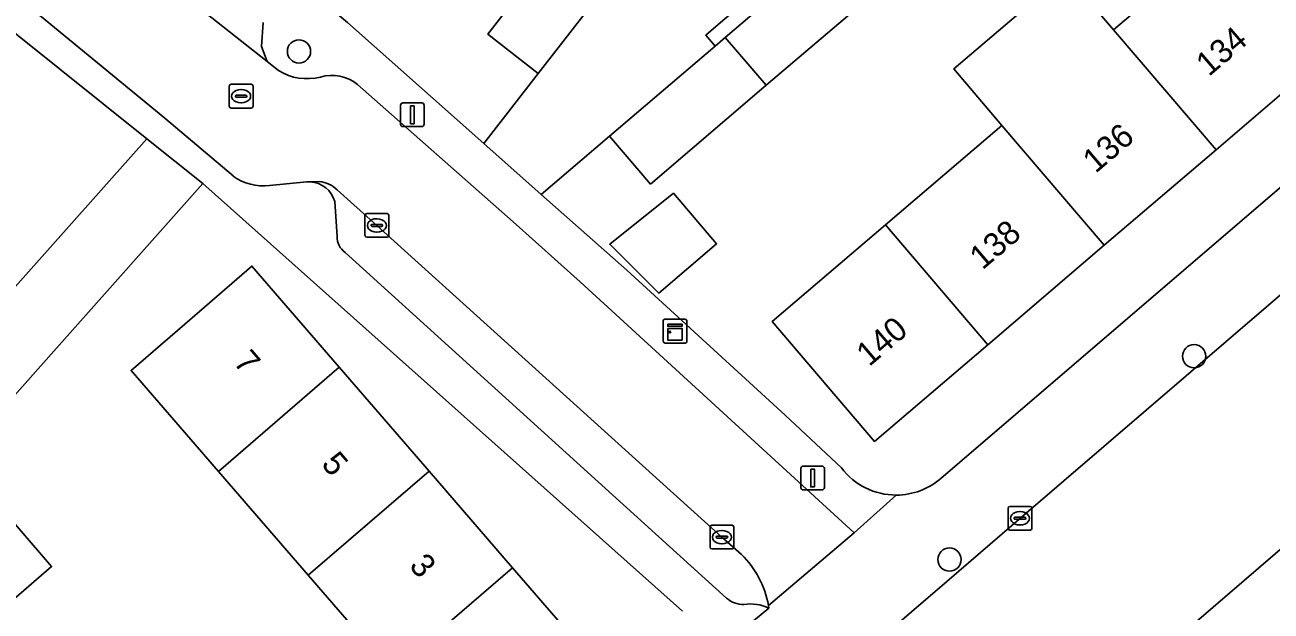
# Model space of a CAD drawing. Extents: x 159039 to 160102, y 381214 to 382524.
# Drawn here: x 159263.7 to 159316.2, y 381504.4 to 381529.1 of the extents above; entities that cross this region are included whole.
import ezdxf

# ---------------------------------------------------------------- set-up
doc = ezdxf.new("R2010")
doc.units = 0
for name, color, linetype in [('IMGEO_Boom', 7, 'Continuous'), ('IMGEO_Erf', 7, 'Continuous'), ('IMGEO_Groenvoorziening', 7, 'Continuous'), ('IMGEO_Kast', 7, 'Continuous'), ('IMGEO_Kolk', 7, 'Continuous'), ('IMGEO_Lichtmast', 7, 'Continuous'), ('IMGEO_Muur', 7, 'Continuous'), ('IMGEO_Pand', 7, 'Continuous'), ('IMGEO_Pand_nummerreeks', 7, 'Continuous'), ('IMGEO_Parkeervlak_open', 7, 'Continuous'), ('IMGEO_Rijbaan_lokaal_gesloten', 7, 'Continuous'), ('IMGEO_Rijbaan_lokaal_open', 7, 'Continuous'), ('IMGEO_Rioolput', 7, 'Continuous'), ('IMGEO_Voetpad_open', 7, 'Continuous')]:
    doc.layers.add(name, color=color, linetype=linetype)

msp = doc.modelspace()

# ---------------------------------------------------------------- linework, layer by layer
at = {"layer": 'IMGEO_Boom'}
for centre in [(159275.265, 381527.96), (159312.94, 381515.129), (159302.643, 381506.571)]:
    msp.add_circle(centre, 0.489, dxfattribs=at)
at = {"layer": 'IMGEO_Erf'}
for points in [[(159319.124, 381547.204), (159313.993, 381542.822), (159309.256, 381538.775), (159304.533, 381534.74), (159299.831, 381530.723), (159294.926, 381526.533), (159290.062, 381522.377), (159288.338, 381524.395), (159285.465, 381521.941), (159289.064, 381518.753), (159295.726, 381512.647), (159298.097, 381510.434)], [(159272.188, 381533.437), (159277.302, 381529.172), (159283.05, 381524.08), (159285.339, 381527.035), (159283.214, 381528.681), (159286.611, 381533.065), (159290.148, 381537.63), (159292.453, 381540.606), (159294.578, 381538.96), (159295.713, 381540.424), (159297.219, 381542.368), (159295.094, 381544.014), (159296.955, 381546.416)], [(159302.294, 381510.002), (159341.644, 381543.745)], [(159247.238, 381500), (159268.86, 381524.286), (159246.942, 381541.865), (159245.158, 381539.557), (159247.25, 381537.94), (159244.299, 381534.121), (159242.207, 381535.738), (159241.376, 381534.663), (159243.468, 381533.046), (159245.588, 381531.374), (159243.761, 381529.009), (159241.624, 381530.66), (159239.781, 381528.274), (159241.687, 381526.801), (159239.335, 381523.759), (159237.43, 381525.232), (159235.947, 381523.313)], [(159318.584, 381527.856), (159313.861, 381523.821), (159309.159, 381519.804), (159304.254, 381515.614), (159299.493, 381511.547), (159295.184, 381516.591), (159299.945, 381520.658), (159304.85, 381524.848), (159302.822, 381527.222), (159307.524, 381531.239), (159309.552, 381528.865), (159314.275, 381532.9), (159319.012, 381536.947)], [(159291.411, 381504.397), (159271.223, 381522.405), (159265.175, 381515.602), (159260.305, 381510.124)], [(159275.659, 381505.911), (159271.878, 381510.282), (159268.199, 381514.535), (159271.076, 381517.02), (159273.285, 381518.928), (159276.961, 381514.671), (159280.739, 381510.298), (159284.252, 381506.23), (159288.078, 381501.8), (159286.026, 381500), (159287.977, 381497.741), (159290.612, 381500), (159291.128, 381500.26)], [(159259.809, 381508.904), (159259.44, 381508.492), (159260.089, 381507.74), (159262.097, 381509.471), (159262.204, 381509.347), (159264.853, 381506.277), (159262.847, 381504.547), (159263.069, 381504.29), (159263.868, 381503.366), (159264.854, 381502.225), (159266.857, 381503.954), (159269.647, 381500.719), (159270.268, 381500), (159273.159, 381496.649), (159273.233, 381496.563), (159274.751, 381497.863), (159280.412, 381491.257), (159280.711, 381491.513), (159284.962, 381495.157), (159280.773, 381500), (159279.176, 381501.846), (159275.659, 381505.911)]]:
    msp.add_lwpolyline(points, dxfattribs=at)
msp.add_lwpolyline([(159292.843, 381519.867), (159290.417, 381517.792), (159288.343, 381519.842), (159291.025, 381521.991)], close=True, dxfattribs=at)
for centre, radius, start, end in [((159300.394, 381512.159), 2.873, 216.8954, 270.1734), ((159300.396, 381512.16), 2.874, 270.1424, 311.3345)]:
    msp.add_arc(centre, radius, start, end, dxfattribs=at)
at = {"layer": 'IMGEO_Groenvoorziening'}
msp.add_lwpolyline([(159298.107, 381532.741), (159300.311, 381534.624), (159299.921, 381535.08), (159297.717, 381533.197), (159292.812, 381529.007), (159292.385, 381528.642), (159292.775, 381528.186), (159293.202, 381528.551)], close=True, dxfattribs=at)
at = {"layer": 'IMGEO_Kast'}
for p, q in [((159290.594, 381515.762), (159290.594, 381516.603)), ((159290.594, 381516.603), (159290.594, 381515.762)), ((159290.669, 381516.687), (159291.51, 381516.687)), ((159291.51, 381516.687), (159290.669, 381516.687)), ((159291.594, 381516.612), (159291.594, 381515.771)), ((159291.594, 381515.771), (159291.594, 381516.612)), ((159291.519, 381515.687), (159290.678, 381515.687)), ((159290.678, 381515.687), (159291.519, 381515.687))]:
    msp.add_line(p, q, dxfattribs=at)
for points in [[(159290.789, 381516.477), (159291.389, 381516.477), (159291.389, 381516.392), (159290.789, 381516.392), (159290.789, 381516.477)], [(159290.789, 381516.302), (159291.389, 381516.302), (159291.389, 381515.813), (159290.789, 381515.813), (159290.789, 381516.302)]]:
    msp.add_lwpolyline(points, dxfattribs=at)
msp.add_circle((159290.873, 381516.151), 0.0377, dxfattribs=at)
for centre, start, end in [((159290.672, 381516.609), 92.4484, 184.2845), ((159290.672, 381516.609), 92.4484, 184.2845), ((159291.516, 381516.609), 2.4484, 94.2845), ((159291.516, 381516.609), 2.4484, 94.2845), ((159290.672, 381515.765), 182.4484, 274.2845), ((159290.672, 381515.765), 182.4484, 274.2845), ((159291.516, 381515.765), 272.4484, 4.2845), ((159291.516, 381515.765), 272.4484, 4.2845)]:
    msp.add_arc(centre, 0.0779, start, end, dxfattribs=at)
at = {"layer": 'IMGEO_Kolk'}
for p, q in [((159278.044, 381520.211), (159278.044, 381521.063)), ((159278.119, 381521.137), (159278.971, 381521.137)), ((159278.346, 381520.68), (159278.744, 381520.68)), ((159278.532, 381520.917), (159278.557, 381520.917)), ((159279.045, 381521.063), (159279.045, 381520.211)), ((159278.971, 381520.137), (159278.119, 381520.137)), ((159278.303, 381520.631), (159278.303, 381520.643)), ((159278.741, 381520.594), (159278.343, 381520.594)), ((159278.555, 381520.357), (159278.53, 381520.357)), ((159278.787, 381520.643), (159278.787, 381520.631)), ((159305.109, 381507.884), (159305.109, 381508.736)), ((159305.184, 381508.81), (159306.036, 381508.81)), ((159305.597, 381508.59), (159305.622, 381508.59)), ((159306.11, 381508.736), (159306.11, 381507.884)), ((159305.368, 381508.304), (159305.368, 381508.316)), ((159305.806, 381508.267), (159305.408, 381508.267)), ((159305.411, 381508.353), (159305.809, 381508.353)), ((159305.852, 381508.316), (159305.852, 381508.304)), ((159292.565, 381507.092), (159292.565, 381507.944)), ((159292.64, 381508.018), (159293.492, 381508.018)), ((159292.867, 381507.561), (159293.265, 381507.561)), ((159293.053, 381507.798), (159293.078, 381507.798)), ((159293.566, 381507.944), (159293.566, 381507.092)), ((159306.036, 381507.81), (159305.184, 381507.81)), ((159305.62, 381508.03), (159305.595, 381508.03)), ((159293.492, 381507.018), (159292.64, 381507.018)), ((159292.824, 381507.512), (159292.824, 381507.524)), ((159293.262, 381507.475), (159292.864, 381507.475)), ((159293.076, 381507.238), (159293.051, 381507.238)), ((159293.308, 381507.524), (159293.308, 381507.512))]:
    msp.add_line(p, q, dxfattribs=at)
for points in [[(159278.044, 381520.211), (159278.044, 381521.063)], [(159278.119, 381521.137), (159278.971, 381521.137)], [(159279.045, 381521.063), (159279.045, 381520.211)], [(159278.971, 381520.137), (159278.119, 381520.137)], [(159305.109, 381507.884), (159305.109, 381508.736)], [(159305.184, 381508.81), (159306.036, 381508.81)], [(159306.11, 381508.736), (159306.11, 381507.884)], [(159292.565, 381507.092), (159292.565, 381507.944)], [(159292.64, 381508.018), (159293.492, 381508.018)], [(159293.566, 381507.944), (159293.566, 381507.092)], [(159306.036, 381507.81), (159305.184, 381507.81)], [(159293.492, 381507.018), (159292.64, 381507.018)]]:
    msp.add_lwpolyline(points, dxfattribs=at)
for centre, radius, start, end in [((159278.121, 381521.061), 0.0765, 91.552, 178.448), ((159278.121, 381521.061), 0.0765, 91.552, 178.448), ((159278.343, 381520.64), 0.0403, 85.8775, 175.7526), ((159278.748, 381520.642), 0.0386, 1.7309, 96.639), ((159278.969, 381521.061), 0.0765, 1.552, 88.448), ((159278.969, 381521.061), 0.0765, 1.552, 88.448), ((159278.121, 381520.213), 0.0765, 181.552, 268.448), ((159278.121, 381520.213), 0.0765, 181.552, 268.448), ((159278.34, 381520.63), 0.0366, 178.938, 274.7102), ((159278.744, 381520.637), 0.043, 264.8664, 352.4533), ((159278.969, 381520.213), 0.0765, 271.552, 358.448), ((159278.969, 381520.213), 0.0765, 271.552, 358.448), ((159305.186, 381508.734), 0.0765, 91.552, 178.448), ((159305.186, 381508.734), 0.0765, 91.552, 178.448), ((159306.034, 381508.734), 0.0765, 1.552, 88.448), ((159306.034, 381508.734), 0.0765, 1.552, 88.448), ((159305.408, 381508.313), 0.0403, 85.8775, 175.7526), ((159305.405, 381508.303), 0.0366, 178.938, 274.7102), ((159305.809, 381508.31), 0.043, 264.8664, 352.4533), ((159305.813, 381508.315), 0.0386, 1.7309, 96.639), ((159292.642, 381507.942), 0.0765, 91.552, 178.448), ((159292.642, 381507.942), 0.0765, 91.552, 178.448), ((159292.864, 381507.521), 0.0403, 85.8775, 175.7526), ((159293.269, 381507.523), 0.0386, 1.7309, 96.639), ((159293.49, 381507.942), 0.0765, 1.552, 88.448), ((159293.49, 381507.942), 0.0765, 1.552, 88.448), ((159305.186, 381507.886), 0.0765, 181.552, 268.448), ((159305.186, 381507.886), 0.0765, 181.552, 268.448), ((159306.034, 381507.886), 0.0765, 271.552, 358.448), ((159306.034, 381507.886), 0.0765, 271.552, 358.448), ((159292.642, 381507.094), 0.0765, 181.552, 268.448), ((159292.642, 381507.094), 0.0765, 181.552, 268.448), ((159292.861, 381507.511), 0.0366, 178.938, 274.7102), ((159293.265, 381507.518), 0.043, 264.8664, 352.4533), ((159293.49, 381507.094), 0.0765, 271.552, 358.448), ((159293.49, 381507.094), 0.0765, 271.552, 358.448)]:
    msp.add_arc(centre, radius, start, end, dxfattribs=at)
for centre, major_axis, ratio, start_param, end_param in [((159278.531, 381520.637), (-0.387, 0.002), 0.722429, 4.712389, 7.853982), ((159278.556, 381520.637), (-0.39, 0.002), 0.717154, 1.570796, 4.712389), ((159305.596, 381508.31), (-0.387, 0.002), 0.722429, 4.712389, 7.853982), ((159305.621, 381508.31), (-0.39, 0.002), 0.717154, 1.570796, 4.712389), ((159293.052, 381507.518), (-0.387, 0.002), 0.722429, 4.712389, 7.853982), ((159293.077, 381507.518), (-0.39, 0.002), 0.717154, 1.570796, 4.712389)]:
    msp.add_ellipse(centre, major_axis=major_axis, ratio=ratio, start_param=start_param, end_param=end_param, dxfattribs=at)
at = {"layer": 'IMGEO_Lichtmast'}
for p, q in [((159279.543, 381524.894), (159279.543, 381525.694)), ((159279.543, 381525.694), (159279.543, 381524.894)), ((159279.643, 381525.794), (159280.433, 381525.794)), ((159280.433, 381525.794), (159279.643, 381525.794)), ((159280.533, 381525.694), (159280.533, 381524.894)), ((159280.533, 381524.894), (159280.533, 381525.694)), ((159280.433, 381524.794), (159279.643, 381524.794)), ((159279.643, 381524.794), (159280.433, 381524.794)), ((159296.387, 381509.605), (159296.387, 381510.405)), ((159296.387, 381510.405), (159296.387, 381509.605)), ((159296.487, 381510.505), (159297.277, 381510.505)), ((159297.277, 381510.505), (159296.487, 381510.505)), ((159297.377, 381510.405), (159297.377, 381509.605)), ((159297.377, 381509.605), (159297.377, 381510.405)), ((159297.277, 381509.505), (159296.487, 381509.505)), ((159296.487, 381509.505), (159297.277, 381509.505))]:
    msp.add_line(p, q, dxfattribs=at)
for points in [[(159279.963, 381525.669), (159280.113, 381525.669), (159280.113, 381524.919), (159279.963, 381524.919), (159279.963, 381525.669)], [(159296.807, 381510.38), (159296.957, 381510.38), (159296.957, 381509.63), (159296.807, 381509.63), (159296.807, 381510.38)]]:
    msp.add_lwpolyline(points, dxfattribs=at)
for centre, start, end in [((159279.643, 381525.694), 90, 180), ((159279.643, 381525.694), 90, 180), ((159280.433, 381525.694), 0, 90), ((159280.433, 381525.694), 360, 90), ((159279.643, 381524.894), 180, 270), ((159279.643, 381524.894), 180, 270), ((159280.433, 381524.894), 270, 0), ((159280.433, 381524.894), 270, 0), ((159296.487, 381510.405), 90, 180), ((159296.487, 381510.405), 90, 180), ((159297.277, 381510.405), 0, 90), ((159297.277, 381510.405), 360, 90), ((159296.487, 381509.605), 180, 270), ((159296.487, 381509.605), 180, 270), ((159297.277, 381509.605), 270, 0), ((159297.277, 381509.605), 270, 0)]:
    msp.add_arc(centre, 0.1, start, end, dxfattribs=at)
at = {"layer": 'IMGEO_Muur'}
for points in [[(159289.064, 381518.753), (159295.726, 381512.647)], [(159265.175, 381515.602), (159260.305, 381510.124)]]:
    msp.add_lwpolyline(points, dxfattribs=at)
at = {"layer": 'IMGEO_Pand'}
for points in [[(159286.611, 381533.065), (159283.214, 381528.681), (159285.339, 381527.035), (159288.735, 381531.419)], [(159298.107, 381532.741), (159293.202, 381528.551), (159294.926, 381526.533), (159299.831, 381530.723)], [(159314.275, 381532.9), (159309.552, 381528.865), (159313.861, 381523.821), (159318.584, 381527.856)], [(159309.552, 381528.865), (159307.524, 381531.239), (159302.822, 381527.222), (159304.85, 381524.848), (159309.159, 381519.804), (159313.861, 381523.821)], [(159294.926, 381526.533), (159293.202, 381528.551), (159292.775, 381528.186), (159288.338, 381524.395), (159290.062, 381522.377)], [(159299.945, 381520.658), (159304.254, 381515.614), (159309.159, 381519.804), (159304.85, 381524.848)], [(159288.343, 381519.842), (159290.417, 381517.792), (159292.843, 381519.867), (159291.025, 381521.991)], [(159299.945, 381520.658), (159295.184, 381516.591), (159299.493, 381511.547), (159304.254, 381515.614)], [(159276.961, 381514.671), (159273.285, 381518.928), (159271.076, 381517.02), (159268.199, 381514.535), (159271.878, 381510.282)], [(159276.961, 381514.671), (159271.878, 381510.282), (159275.659, 381505.911), (159280.739, 381510.298)], [(159279.176, 381501.846), (159284.252, 381506.23), (159280.739, 381510.298), (159275.659, 381505.911)], [(159262.097, 381509.471), (159260.089, 381507.74), (159260.198, 381507.614), (159262.847, 381504.547), (159264.853, 381506.277), (159262.204, 381509.347)], [(159279.176, 381501.846), (159280.773, 381500), (159284.962, 381495.157), (159287.977, 381497.741), (159286.026, 381500), (159288.078, 381501.8), (159284.252, 381506.23)]]:
    msp.add_lwpolyline(points, close=True, dxfattribs=at)
at = {"layer": 'IMGEO_Parkeervlak_open'}
for points in [[(159266.264, 381533.753), (159269.992, 381530.657), (159273.92, 381527.538), (159273.694, 381528.174), (159273.765, 381529.174)], [(159276.122, 381522.482), (159275.749, 381522.476)], [(159293.886, 381506.79), (159293.067, 381507.518), (159278.546, 381520.639), (159276.873, 381522.136)], [(159276.774, 381521.65), (159276.875, 381520.175)], [(159277.208, 381519.502), (159293.257, 381504.947)], [(159295.042, 381504.532), (159295.023, 381504.635)]]:
    msp.add_lwpolyline(points, dxfattribs=at)
for centre, radius, start, end in [((159275.658, 381521.314), 1.166, 16.7628, 85.5098), ((159275.998, 381521.225), 1.263, 46.1617, 84.3655), ((159277.67, 381520.15), 0.796, 178.1731, 234.4793), ((159291.115, 381503.951), 3.967, 9.9339, 45.6993), ((159293.977, 381505.784), 1.104, 229.291, 270.5792), ((159294.28, 381502.931), 1.773, 64.5419, 99.472)]:
    msp.add_arc(centre, radius, start, end, dxfattribs=at)
at = {"layer": 'IMGEO_Rijbaan_lokaal_gesloten'}
msp.add_lwpolyline([(159302.526, 381505.654), (159297.968, 381501.732), (159295.931, 381500), (159281.518, 381487.748), (159278.677, 381485.329), (159274.306, 381481.608), (159279.589, 381475.401), (159281.201, 381476.782), (159287.127, 381481.79), (159288.533, 381483.013), (159301.064, 381493.711), (159302.188, 381494.631), (159308.43, 381500), (159317.66, 381507.94), (159332.693, 381520.763), (159327.779, 381527.216), (159319.433, 381520.175), (159305.767, 381508.444)], close=True, dxfattribs=at)
at = {"layer": 'IMGEO_Rijbaan_lokaal_open'}
for points in [[(159230.284, 381555.722), (159238.362, 381549.804), (159239.339, 381549.072), (159242.969, 381546.354), (159248.2, 381542.427), (159256.706, 381535.766), (159269.617, 381525.152), (159272.501, 381522.717)], [(159274.407, 381527.151), (159273.92, 381527.538), (159269.992, 381530.657), (159266.264, 381533.753), (159266.069, 381533.916), (159259.958, 381538.894)], [(159295.023, 381504.635), (159298.627, 381507.7), (159287.093, 381518.26), (159284.284, 381520.792), (159277.726, 381526.565)], [(159274.026, 381522.318), (159275.602, 381522.47), (159275.749, 381522.476), (159276.122, 381522.482)], [(159276.873, 381522.136), (159278.546, 381520.639), (159293.067, 381507.518), (159293.886, 381506.79)]]:
    msp.add_lwpolyline(points, dxfattribs=at)
for centre, radius, start, end in [((159275.61, 381529.11), 2.299, 238.4529, 284.0499), ((159276.656, 381525.285), 1.668, 50.1151, 107.0246), ((159273.749, 381524.373), 2.074, 233.0028, 277.6729), ((159275.998, 381521.225), 1.263, 46.1617, 84.3655), ((159291.115, 381503.951), 3.967, 9.9339, 45.6993)]:
    msp.add_arc(centre, radius, start, end, dxfattribs=at)
at = {"layer": 'IMGEO_Rioolput'}
for p, q in [((159272.33, 381525.649), (159272.33, 381526.501)), ((159272.405, 381526.575), (159273.257, 381526.575)), ((159273.331, 381526.501), (159273.331, 381525.649)), ((159272.589, 381526.069), (159272.589, 381526.081)), ((159273.027, 381526.032), (159272.629, 381526.032)), ((159272.632, 381526.118), (159273.03, 381526.118)), ((159272.818, 381526.355), (159272.843, 381526.355)), ((159273.073, 381526.081), (159273.073, 381526.069)), ((159273.257, 381525.575), (159272.405, 381525.575)), ((159272.841, 381525.795), (159272.816, 381525.795))]:
    msp.add_line(p, q, dxfattribs=at)
for points in [[(159272.33, 381525.649), (159272.33, 381526.501)], [(159272.405, 381526.575), (159273.257, 381526.575)], [(159273.331, 381526.501), (159273.331, 381525.649)], [(159273.257, 381525.575), (159272.405, 381525.575)]]:
    msp.add_lwpolyline(points, dxfattribs=at)
for centre, radius, start, end in [((159272.407, 381526.499), 0.0765, 91.552, 178.448), ((159272.407, 381526.499), 0.0765, 91.552, 178.448), ((159273.255, 381526.499), 0.0765, 1.552, 88.448), ((159273.255, 381526.499), 0.0765, 1.552, 88.448), ((159272.629, 381526.078), 0.0403, 85.8775, 175.7526), ((159272.626, 381526.068), 0.0366, 178.938, 274.7102), ((159273.03, 381526.075), 0.043, 264.8664, 352.4533), ((159273.034, 381526.08), 0.0386, 1.7309, 96.639), ((159272.407, 381525.651), 0.0765, 181.552, 268.448), ((159272.407, 381525.651), 0.0765, 181.552, 268.448), ((159273.255, 381525.651), 0.0765, 271.552, 358.448), ((159273.255, 381525.651), 0.0765, 271.552, 358.448)]:
    msp.add_arc(centre, radius, start, end, dxfattribs=at)
for centre, major_axis, ratio, start_param, end_param in [((159272.817, 381526.075), (-0.387, 0.002), 0.722429, 4.712389, 7.853982), ((159272.842, 381526.075), (-0.39, 0.002), 0.717154, 1.570796, 4.712389)]:
    msp.add_ellipse(centre, major_axis=major_axis, ratio=ratio, start_param=start_param, end_param=end_param, dxfattribs=at)
at = {"layer": 'IMGEO_Voetpad_open'}
for points in [[(159403.253, 381581.19), (159401.441, 381579.651), (159391.641, 381571.315), (159381.263, 381562.391), (159379.14, 381560.565), (159377.401, 381559.069), (159375.25, 381557.212), (159372.533, 381554.867), (159361.516, 381545.448), (159356.286, 381541.009), (159356.146, 381540.888), (159351.483, 381536.862), (159349.151, 381534.849), (159346.704, 381532.736), (159334.842, 381522.599), (159332.693, 381520.763), (159317.66, 381507.94), (159308.43, 381500), (159302.188, 381494.631), (159301.064, 381493.711)], [(159218.334, 381561.045), (159223.584, 381558.124), (159228.043, 381556.036), (159241.577, 381546.081), (159242.332, 381545.526), (159242.889, 381545.116), (159245.322, 381543.165), (159246.942, 381541.865), (159268.86, 381524.286), (159271.223, 381522.405), (159291.411, 381504.397)], [(159272.501, 381522.717), (159269.617, 381525.152), (159256.706, 381535.766), (159248.2, 381542.427), (159242.969, 381546.354), (159239.339, 381549.072), (159238.362, 381549.804), (159230.284, 381555.722)], [(159349.696, 381550.65), (159341.644, 381543.745), (159302.294, 381510.002)], [(159298.097, 381510.434), (159295.726, 381512.647), (159289.064, 381518.753), (159285.465, 381521.941), (159283.05, 381524.08), (159277.302, 381529.172), (159272.188, 381533.437)], [(159288.735, 381531.419), (159285.339, 381527.035), (159283.05, 381524.08), (159285.465, 381521.941), (159288.338, 381524.395), (159292.775, 381528.186), (159292.385, 381528.642), (159292.812, 381529.007), (159297.717, 381533.197)], [(159273.765, 381529.174), (159273.694, 381528.174), (159273.92, 381527.538), (159274.407, 381527.151)], [(159277.726, 381526.565), (159284.284, 381520.792), (159287.093, 381518.26), (159298.627, 381507.7), (159300.403, 381509.286)], [(159260.305, 381510.124), (159265.175, 381515.602), (159271.223, 381522.405), (159268.86, 381524.286), (159247.238, 381500), (159242.769, 381494.981)], [(159275.749, 381522.476), (159275.602, 381522.47), (159274.026, 381522.318)], [(159276.875, 381520.175), (159276.774, 381521.65)], [(159232.898, 381449.89), (159232.488, 381448.686), (159230.747, 381444.157), (159230.307, 381443.034), (159232.903, 381442.592), (159233.403, 381442.507), (159235.381, 381448.161), (159241.329, 381453.344), (159243.638, 381455.319), (159245.889, 381457.245), (159250.208, 381460.939), (159269.659, 381477.653), (159272.211, 381479.825), (159274.306, 381481.608), (159278.677, 381485.329), (159281.518, 381487.748), (159295.931, 381500), (159297.968, 381501.732), (159302.526, 381505.654), (159305.767, 381508.444), (159319.433, 381520.175)], [(159293.257, 381504.947), (159277.208, 381519.502)], [(159300.403, 381509.286), (159298.627, 381507.7), (159295.023, 381504.635), (159295.042, 381504.532), (159292.222, 381502.192)], [(159292.222, 381502.192), (159295.042, 381504.532)]]:
    msp.add_lwpolyline(points, dxfattribs=at)
for centre, radius, start, end in [((159275.61, 381529.11), 2.299, 238.4529, 284.0499), ((159276.656, 381525.285), 1.668, 50.1151, 107.0246), ((159273.749, 381524.373), 2.074, 233.0028, 277.6729), ((159275.658, 381521.314), 1.166, 16.7628, 85.5098), ((159277.67, 381520.15), 0.796, 178.1731, 234.4793), ((159300.394, 381512.159), 2.873, 216.8954, 270.1734), ((159300.396, 381512.16), 2.874, 270.1424, 311.3345), ((159293.977, 381505.784), 1.104, 229.291, 270.5792), ((159294.28, 381502.931), 1.773, 64.5419, 99.472)]:
    msp.add_arc(centre, radius, start, end, dxfattribs=at)

# ---------------------------------------------------------------- texts
at = {"layer": 'IMGEO_Pand_nummerreeks'}
for s, rotation, p in [('134', 40.5071, (159313.558, 381526.877)), ('136', 40.5081, (159308.792, 381522.805)), ('138', 40.5071, (159304.029, 381518.737)), ('140', 40.5071, (159299.263, 381514.666)), ('7', 310.8173, (159272.471, 381514.85)), ('5', 310.8163, (159276.17, 381510.569)), ('3', 310.8163, (159279.868, 381506.287))]:
    msp.add_text(s, height=1, rotation=rotation, dxfattribs=at).set_placement(p)

doc.saveas('drawing.dxf')
